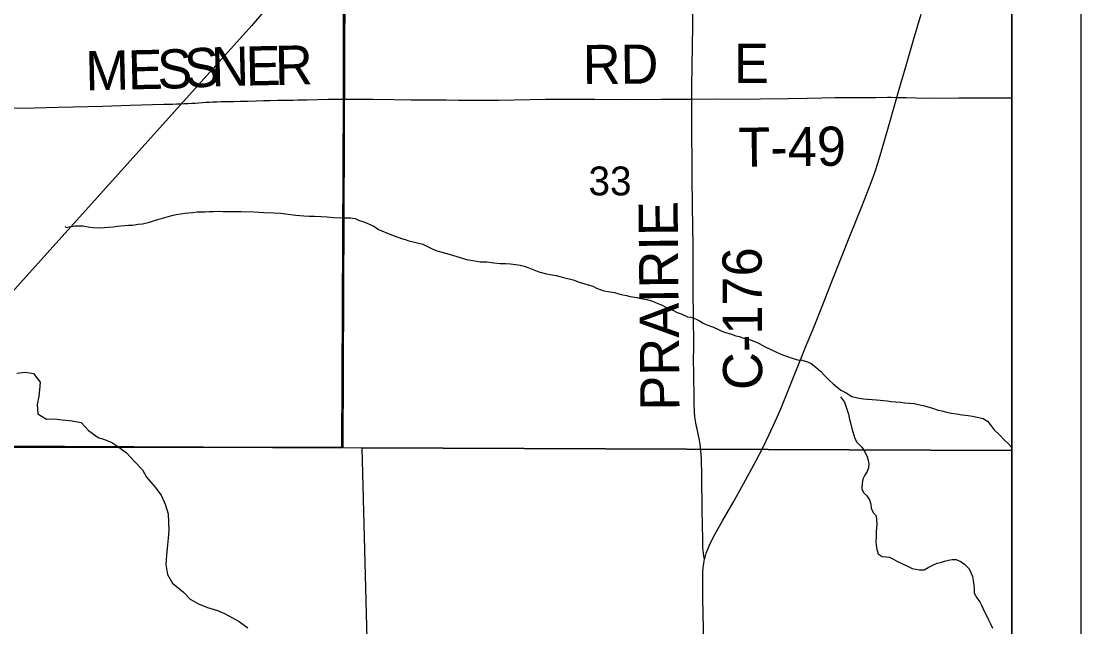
# Model space of a CAD drawing. Extents: x 0 to 34, y 0 to 22.
# Drawn here: x 7.463 to 9, y 15 to 15.878 of the extents above; entities that cross this region are included whole.
import ezdxf

# ---------------------------------------------------------------- set-up
doc = ezdxf.new("R2010")
doc.units = 0
for name, color, linetype in [('GM_X_County_Road', 7, 'Continuous'), ('GM_X_County_Road_Text', 7, 'Continuous'), ('GM_X_Minor_River', 7, 'Continuous'), ('GM_X_Section', 7, 'Continuous'), ('GM_X_Section_Text', 7, 'Continuous'), ('GM_X_State_Route', 7, 'Continuous'), ('GM_X_Township_Road', 7, 'Continuous'), ('GM_X_Township_Road_Text', 7, 'Continuous'), ('GM_X_Unincorporated', 7, 'Continuous'), ('SH_Data', 7, 'Continuous')]:
    doc.layers.add(name, color=color, linetype=linetype)

msp = doc.modelspace()

# ---------------------------------------------------------------- linework, layer by layer
at = {"layer": 'GM_X_County_Road'}
for points in [[(8.4359, 15.7655), (8.436, 15.7861), (8.4362, 15.8109), (8.4367, 15.845), (8.4371, 15.8698), (8.4374, 15.8884)], [(8.4543, 15.0977), (8.4533, 15.1024), (8.4525, 15.1065), (8.4519, 15.1143), (8.4516, 15.1264), (8.4509, 15.1692), (8.4503, 15.2187), (8.4498, 15.2434), (8.4489, 15.2557), (8.4478, 15.2648), (8.4467, 15.2708), (8.4429, 15.2889), (8.4422, 15.2922), (8.4416, 15.2956), (8.4411, 15.2986), (8.4404, 15.3042), (8.4398, 15.3116), (8.4394, 15.3244), (8.439, 15.3403), (8.4386, 15.3566), (8.4385, 15.3696), (8.4384, 15.3854), (8.4385, 15.4067), (8.438, 15.4526), (8.4377, 15.4836), (8.4377, 15.5054), (8.4377, 15.5364), (8.4376, 15.555), (8.4374, 15.5798), (8.437, 15.6108), (8.4368, 15.6182), (8.4364, 15.6451), (8.4363, 15.6627), (8.4358, 15.7271), (8.4359, 15.7655)]]:
    msp.add_lwpolyline(points, dxfattribs=at)
at = {"layer": 'GM_X_Minor_River'}
for points in [[(8.4344, 16.8906), (8.4339, 16.505), (8.1234, 16.2526), (7.7972, 15.8716), (7.3114, 15.3314), (7.166, 15.2871), (6.9088, 15.1189), (6.3982, 15.0073)], [(7.5268, 15.5804), (7.5281, 15.5791), (7.533, 15.5802), (7.541, 15.5813), (7.5478, 15.5817), (7.5527, 15.5813), (7.5626, 15.5794), (7.5675, 15.579), (7.5781, 15.5786), (7.5838, 15.579), (7.5898, 15.5794), (7.5966, 15.5801), (7.6027, 15.5812), (7.6186, 15.5827), (7.6243, 15.5827), (7.6326, 15.5838), (7.6391, 15.5846), (7.6474, 15.5865), (7.6523, 15.5876), (7.6614, 15.5906), (7.6818, 15.5963), (7.6879, 15.5978), (7.6939, 15.599), (7.7004, 15.6001), (7.7064, 15.6005), (7.7121, 15.6008), (7.7182, 15.6016), (7.7246, 15.6016), (7.7299, 15.6019), (7.7356, 15.6023), (7.742, 15.6023), (7.7507, 15.6027), (7.7557, 15.6023), (7.7822, 15.6022), (7.8003, 15.6018), (7.8079, 15.6014), (7.8143, 15.601), (7.8295, 15.6003), (7.8397, 15.5999), (7.8462, 15.5991), (7.8613, 15.5972), (7.873, 15.596), (7.8806, 15.5956), (7.8886, 15.5956), (7.8977, 15.5952), (7.9068, 15.5944), (7.9162, 15.5937), (7.9306, 15.5932), (7.9405, 15.5929), (7.9473, 15.5921), (7.9522, 15.5898), (7.9602, 15.5871), (7.9745, 15.581), (7.9814, 15.5761), (8.0003, 15.5684), (8.0147, 15.5631), (8.02, 15.5616), (8.0253, 15.5597), (8.0458, 15.5547), (8.0571, 15.549), (8.0647, 15.5455), (8.084, 15.5406), (8.0996, 15.5356), (8.109, 15.5329), (8.1181, 15.531), (8.1287, 15.5295), (8.1386, 15.5291), (8.1484, 15.5279), (8.1579, 15.5271), (8.1662, 15.5267), (8.173, 15.5263), (8.1799, 15.5256), (8.1867, 15.5244), (8.1927, 15.5229), (8.1996, 15.5206), (8.2064, 15.5176), (8.214, 15.5149), (8.2249, 15.5118), (8.2303, 15.5107), (8.239, 15.5095), (8.2499, 15.5065), (8.2636, 15.503), (8.2723, 15.4996), (8.292, 15.4939), (8.2973, 15.4912), (8.3083, 15.4874), (8.3144, 15.4862), (8.3234, 15.4847), (8.3299, 15.4828), (8.3359, 15.4816), (8.3412, 15.4805), (8.3465, 15.4789), (8.3564, 15.4774), (8.3617, 15.4763), (8.3704, 15.4747), (8.3787, 15.4724), (8.3867, 15.469), (8.3916, 15.4667), (8.3973, 15.464), (8.4026, 15.4614), (8.4083, 15.4591)], [(8.4083, 15.4591), (8.4144, 15.456), (8.4204, 15.4537), (8.4295, 15.4495), (8.4344, 15.4488), (8.4413, 15.4465), (8.4469, 15.4438), (8.4523, 15.4404), (8.4576, 15.4377), (8.4674, 15.4343), (8.4746, 15.4312), (8.4795, 15.4286), (8.4848, 15.4266), (8.492, 15.4247), (8.4996, 15.4221), (8.5045, 15.4209), (8.511, 15.4186), (8.5205, 15.4163), (8.5273, 15.4137), (8.5337, 15.4106), (8.5413, 15.4064), (8.5587, 15.398), (8.5674, 15.3942), (8.5746, 15.3919), (8.5799, 15.39), (8.589, 15.3873), (8.5955, 15.3866), (8.6034, 15.3843), (8.6087, 15.382), (8.6159, 15.3763), (8.6224, 15.3706), (8.6292, 15.3633), (8.6345, 15.358), (8.6406, 15.3523), (8.652, 15.3431), (8.6595, 15.339), (8.6679, 15.334), (8.6762, 15.3321), (8.6849, 15.3306), (8.6906, 15.3302), (8.6974, 15.3298), (8.7035, 15.329), (8.7088, 15.3286), (8.7137, 15.3282), (8.719, 15.3275), (8.7251, 15.3267), (8.7383, 15.3255), (8.7448, 15.3248), (8.7584, 15.3236), (8.7648, 15.3224), (8.7735, 15.3205), (8.7849, 15.3171), (8.7932, 15.314), (8.7982, 15.3129), (8.805, 15.311), (8.8126, 15.3098), (8.8198, 15.309), (8.8277, 15.3075), (8.8368, 15.3064), (8.8429, 15.3056), (8.8497, 15.3041), (8.8584, 15.3021), (8.8645, 15.2983), (8.8686, 15.2934), (8.8743, 15.2858), (8.8819, 15.2782), (8.8891, 15.2705), (8.894, 15.266), (8.8994, 15.2603), (8.9, 15.2594)], [(7.4569, 15.3678), (7.4686, 15.3694), (7.4811, 15.3672), (7.4906, 15.3547), (7.4895, 15.3437), (7.4885, 15.3342), (7.4862, 15.3216), (7.4874, 15.3087), (7.4996, 15.3012), (7.5113, 15.3013), (7.5223, 15.3002), (7.5371, 15.2984), (7.5499, 15.2961), (7.5609, 15.2848), (7.5746, 15.2746), (7.5841, 15.2716), (7.5943, 15.2671), (7.6049, 15.2603), (7.6156, 15.2524), (7.627, 15.2403), (7.6392, 15.2275), (7.6449, 15.2169), (7.6567, 15.2029), (7.6662, 15.1908), (7.6719, 15.1775), (7.6762, 15.1635), (7.6766, 15.1514), (7.6774, 15.1396), (7.6763, 15.1286), (7.6752, 15.1187), (7.6738, 15.1039), (7.6727, 15.0903), (7.6754, 15.0758), (7.6827, 15.063), (7.6983, 15.0501), (7.7081, 15.0399), (7.7203, 15.0332), (7.7332, 15.0279), (7.7479, 15.0234), (7.7582, 15.0193), (7.7696, 15.0129), (7.7794, 15.0076), (7.7919, 14.9982)], [(8.6516, 15.3336), (8.6573, 15.3257), (8.6603, 15.3169), (8.663, 15.3085), (8.6641, 15.3028), (8.666, 15.2956), (8.6679, 15.2873), (8.6721, 15.2732), (8.6752, 15.2675), (8.6824, 15.2603), (8.6869, 15.2538), (8.6903, 15.2466), (8.6915, 15.2416), (8.6926, 15.2359), (8.6919, 15.2306), (8.69, 15.2253), (8.6866, 15.22), (8.684, 15.2139), (8.6828, 15.2078), (8.6825, 15.2006), (8.6844, 15.1953), (8.6897, 15.1899), (8.6935, 15.1838), (8.6954, 15.1778), (8.6961, 15.1717), (8.6988, 15.1656), (8.703, 15.1606), (8.7041, 15.1489), (8.7034, 15.1382), (8.703, 15.1302), (8.7026, 15.123), (8.7034, 15.1181), (8.7042, 15.112), (8.7061, 15.1055), (8.7121, 15.1017), (8.7171, 15.1013), (8.7224, 15.1006), (8.7273, 15.0983), (8.7341, 15.0945), (8.7394, 15.0922), (8.7504, 15.0868), (8.7553, 15.0846), (8.7659, 15.0823), (8.7728, 15.0826), (8.7788, 15.0857), (8.7864, 15.0898), (8.7917, 15.0921), (8.7966, 15.0932), (8.8023, 15.0951), (8.8083, 15.0963), (8.8133, 15.0974), (8.8193, 15.0974), (8.8265, 15.0939), (8.8314, 15.0905), (8.8379, 15.084), (8.8405, 15.0787), (8.8428, 15.073), (8.844, 15.0669), (8.8447, 15.0601), (8.8451, 15.0544), (8.8455, 15.0487), (8.8493, 15.0418), (8.8535, 15.0361), (8.8561, 15.0312), (8.8599, 15.0224), (8.863, 15.016), (8.866, 15.0099), (8.869, 15.0042), (8.8717, 14.9977)]]:
    msp.add_lwpolyline(points, dxfattribs=at)
at = {"layer": 'GM_X_Section'}
for points in [[(7.9341, 16.2671), (7.9294, 15.2601), (6.9531, 15.2604), (6.9228, 15.2602), (6.9303, 16.2282), (7.503, 16.2382)], [(6.9531, 15.2604), (7.9294, 15.2601), (7.9571, 15.2595), (7.9839, 14.2421), (6.9669, 14.2596)]]:
    msp.add_lwpolyline(points, close=True, dxfattribs=at)
at = {"layer": 'GM_X_State_Route'}
for points in [[(8.4524, 15.0857), (8.4526, 15.0888), (8.4536, 15.0948), (8.4543, 15.0977), (8.455, 15.1008), (8.4568, 15.1067), (8.4589, 15.1124), (8.4626, 15.1208), (8.4697, 15.1345), (8.4802, 15.1534), (8.4957, 15.1803), (8.5108, 15.2074), (8.5286, 15.2402), (8.5387, 15.2595), (8.5482, 15.279), (8.5574, 15.2987), (8.5647, 15.3158), (8.5832, 15.3618), (8.5924, 15.3848), (8.6018, 15.4078), (8.6113, 15.4307), (8.6262, 15.4683), (8.6399, 15.503), (8.6649, 15.5666), (8.673, 15.5868), (8.6822, 15.6098), (8.696, 15.6444), (8.7013, 15.659), (8.7061, 15.6737), (8.7115, 15.6916), (8.7192, 15.7185), (8.733, 15.7679), (8.7369, 15.7813), (8.7465, 15.8141), (8.7579, 15.8529), (8.7685, 15.8886)], [(8.456, 14.7703), (8.4559, 14.7753), (8.4556, 14.8002), (8.4552, 14.8157), (8.4552, 14.825), (8.4547, 14.8592), (8.4545, 14.8809), (8.4542, 14.9058), (8.4538, 14.9213), (8.4532, 14.9679), (8.4526, 14.9989), (8.4524, 15.0176), (8.4519, 15.0424), (8.4516, 15.0672), (8.4519, 15.0796), (8.4524, 15.0857)]]:
    msp.add_lwpolyline(points, dxfattribs=at)
at = {"layer": 'GM_X_Township_Road'}
for points in [[(5.7675, 15.2711), (6.9226, 15.2644), (7.9283, 15.2595), (7.9306, 15.7658), (7.9301, 16.1134), (7.9298, 16.2367), (7.9298, 16.2686), (7.9297, 16.3619), (7.9163, 17.252), (8.4218, 17.2637), (8.9, 17.2634), (8.9, 20.9)], [(7.4516, 15.752), (7.4826, 15.7527), (7.5168, 15.7536), (7.5816, 15.7552), (7.6212, 15.7565), (7.6698, 15.7579), (7.6825, 15.758), (7.6885, 15.7583), (7.694, 15.7586), (7.6996, 15.7588), (7.7051, 15.7591), (7.7106, 15.7593), (7.7155, 15.7597), (7.7205, 15.76), (7.7313, 15.7608), (7.7361, 15.7611), (7.7405, 15.7613), (7.7443, 15.7614), (7.7471, 15.7615), (7.7527, 15.7617), (7.7599, 15.7618), (7.7708, 15.7621), (7.7808, 15.7623), (7.7913, 15.7626), (7.8038, 15.7629), (7.815, 15.7631), (7.8237, 15.7633), (7.8355, 15.7636), (7.8375, 15.7637), (7.8573, 15.764), (7.8643, 15.7641), (7.8771, 15.7644), (7.9082, 15.7651), (7.9308, 15.7653), (7.9318, 15.7653)], [(7.9318, 15.7653), (7.9523, 15.7654), (7.9737, 15.7655), (8.0039, 15.7649), (8.0286, 15.7645), (8.0791, 15.7642), (8.0975, 15.7638), (8.1087, 15.7638), (8.1194, 15.7638), (8.1288, 15.7637), (8.1394, 15.7637), (8.1552, 15.764), (8.2236, 15.7651), (8.2952, 15.7654), (8.345, 15.7648), (8.3917, 15.7651), (8.4166, 15.7653), (8.4327, 15.7655), (8.4359, 15.7655)], [(8.4359, 15.7655), (8.4699, 15.7656), (8.5134, 15.7654), (8.5351, 15.7656), (8.5753, 15.7663), (8.6032, 15.7668), (8.6246, 15.7673), (8.643, 15.7675), (8.6647, 15.7676), (8.702, 15.7678), (8.7195, 15.7681), (8.7247, 15.768), (8.732, 15.7679), (8.733, 15.7679)], [(8.733, 15.7679), (8.738, 15.7677), (8.7466, 15.7675), (8.7609, 15.767), (8.7827, 15.7668), (8.8229, 15.767), (8.8509, 15.7672), (8.8819, 15.7671), (8.9, 15.7672)]]:
    msp.add_lwpolyline(points, dxfattribs=at)
msp.add_lwpolyline([(5.7705, 14.1), (8.9, 14.1), (8.9, 17.2634), (8.4218, 17.2637), (7.9163, 17.252), (7.9297, 16.3619), (7.9298, 16.2686), (7.9298, 16.2367), (7.9301, 16.1134), (7.9306, 15.7658), (7.9283, 15.2595), (6.9226, 15.2644), (5.7675, 15.2711), (5.7694, 14.855)], close=True, dxfattribs=at)
at = {"layer": 'GM_X_Unincorporated'}
for points in [[(8.9, 15.2555), (8.9, 16.2628), (7.9341, 16.2671), (7.9294, 15.2601), (7.9571, 15.2595)], [(8.9, 14.2334), (8.9, 15.2555), (7.9571, 15.2595), (7.9839, 14.2421)]]:
    msp.add_lwpolyline(points, close=True, dxfattribs=at)
at = {"layer": 'SH_Data'}
for p, q in [((9, 21), (9, 14)), ((8.9, 20.9), (8.9, 14.1))]:
    msp.add_line(p, q, dxfattribs=at)

# ---------------------------------------------------------------- texts
at = {"layer": 'GM_X_County_Road_Text'}
for s, rotation, p in [('PRAIRIE', 90.527, (8.418, 15.3137)), ('C-176', 90.2734, (8.538, 15.3435))]:
    msp.add_text(s, height=0.05682, rotation=rotation, dxfattribs=at).set_placement(p)
at = {"layer": 'GM_X_Section_Text'}
msp.add_text('33', height=0.04186, rotation=0, dxfattribs=at).set_placement((8.286, 15.6257))
at = {"layer": 'GM_X_Township_Road_Text'}
for s, height, rotation, p in [('M', 0.0568, 1.2318, (7.5567, 15.778)), ('E', 0.0568, 1.2322, (7.6183, 15.7793)), ('S', 0.0568, 1.4886, (7.6611, 15.7802)), ('S', 0.0568, 3.5436, (7.7016, 15.7813)), ('N', 0.0568, 1.4591, (7.7393, 15.7837)), ('E', 0.0568, 1.1979, (7.7892, 15.7849)), ('R', 0.0568, 1.1976, (7.8317, 15.7858)), ('RD', 0.05682, 0.4777, (8.2778, 15.7871)), ('E', 0.0568, 0, (8.4968, 15.7888)), ('T-49', 0.05682, 0.7052, (8.5035, 15.667))]:
    msp.add_text(s, height=height, rotation=rotation, dxfattribs=at).set_placement(p)

doc.saveas('drawing.dxf')
